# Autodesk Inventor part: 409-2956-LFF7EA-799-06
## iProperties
Created: 2010-11
Part Number: 409-2956-LFF7EA-799-06
Material: 3/4" OD TUBE - SS
Document SubType Name: Modeling
Designer: S. Boerckel
Engineer: Steve Boerckel
Mass: 340.704 g
Surface Area: 512.603 cm^2
Volume: 42.1664 cm^3
Density: 8.08 g/cm^3
Description: DRAIN TUBING
User Status: CUT/TUBE BEND
Length: 17.945 in
Author: S. Boerckel
Revision Number: 0
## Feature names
1. Sweep2
